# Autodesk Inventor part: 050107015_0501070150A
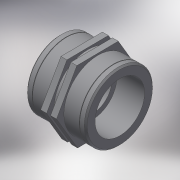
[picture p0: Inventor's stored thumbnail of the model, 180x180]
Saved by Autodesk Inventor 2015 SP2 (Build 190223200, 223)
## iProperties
Created: 2017-05
Part Number: 050107015_0501070150A
Material: Generic
Description: PLASSON SOCKET PP 1.1/2"-1.1/2"
Document SubType Name: Modeling
Designer: KIM
Density: 1 g/cm^3
Appearance: Default
Author: KIM
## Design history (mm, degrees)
derived "050107.ipt"
feature "Solid1::050107.ipt"
tag "TaggingFeature1"
body "Solid1"
other parameters: "d0" = 54, "d2" = 44.845, "d3" = 25, "d5" = 65, "d6" = 61.75, "d7" = 35.876, "d14" = 0, "d15" = 1.34535, "d18" = 5.4, "d19" = 1.8, "d20" = 0.5, "d21" = 0.5, "d22" = 61.75, "Rp_" = 44.845, "H_" = 54, "l_2" = 25, "E_" = 65
